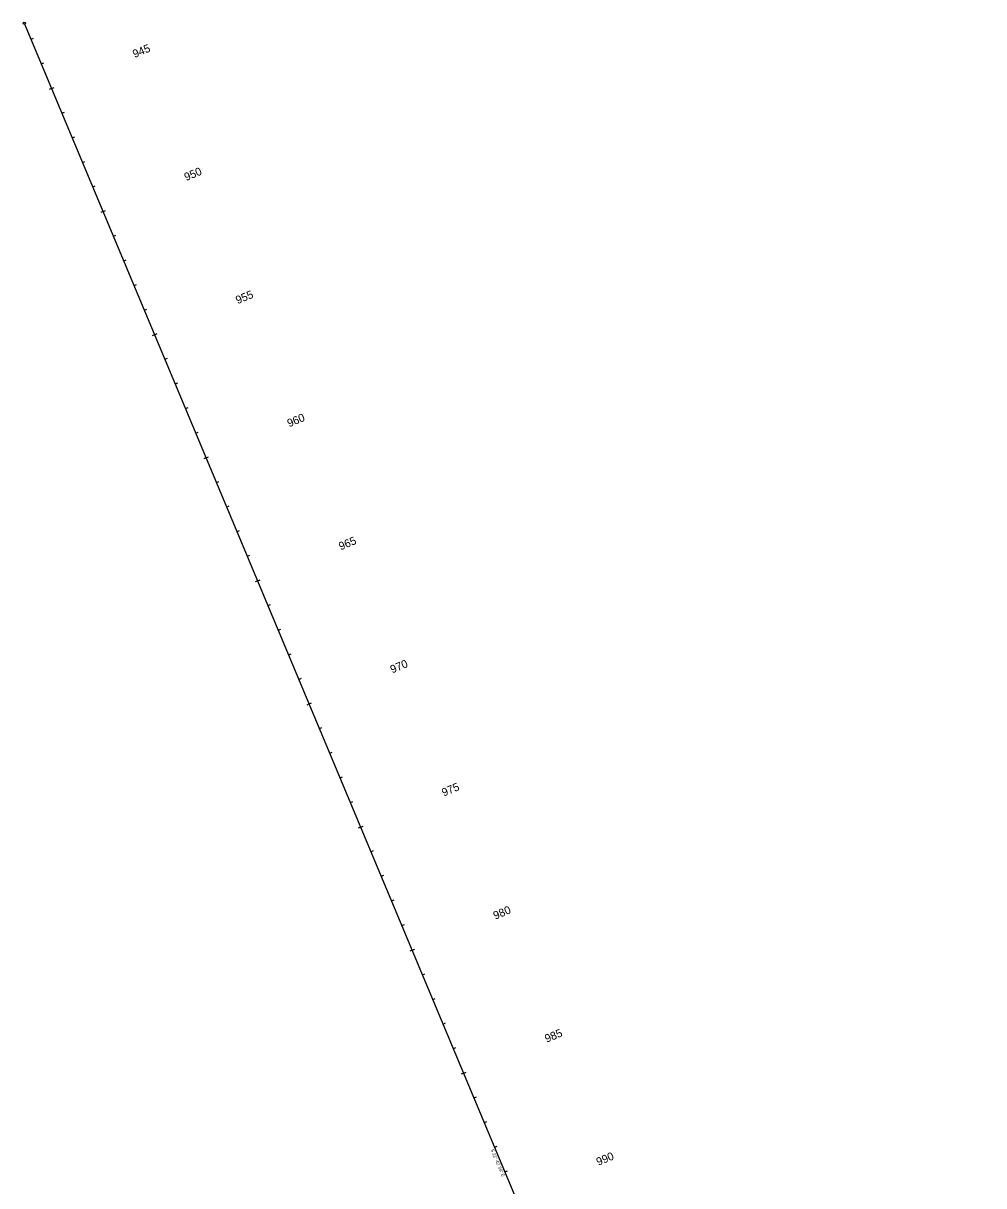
# Model space of a CAD drawing. Extents: x 2819977 to 2827606, y 116785 to 150320.
# Drawn here: x 2821722 to 2825322, y 121023 to 125379 of the extents above; entities that cross this region are included whole.
import ezdxf

# ---------------------------------------------------------------- set-up
doc = ezdxf.new("R2010")
doc.units = 0
for name, color, linetype in [('Modeling-Contours-Minor-Existing', 7, 'Continuous'), ('Modeling-Flow Arrows-Existing', 7, 'Continuous'), ('Modeling-Spot-Existing', 7, 'Continuous')]:
    doc.layers.add(name, color=color, linetype=linetype)

msp = doc.modelspace()

# ---------------------------------------------------------------- linework, layer by layer
at = {"layer": 'Modeling-Flow Arrows-Existing'}
for p, q in [((2821725.8, 125379.3), (2825322, 116789)), ((2821750.9, 125319.2), (2821760.1, 125323.1)), ((2821789.5, 125227), (2821798.8, 125230.8)), ((2821828.2, 125134.7), (2821818.9, 125130.9)), ((2821828.2, 125134.7), (2821837.4, 125138.6)), ((2821866.8, 125042.5), (2821876, 125046.4)), ((2821905.4, 124950.3), (2821914.6, 124954.1)), ((2821944, 124858), (2821953.2, 124861.9)), ((2821982.6, 124765.8), (2821991.8, 124769.6)), ((2822021.2, 124673.5), (2822012, 124669.7)), ((2822021.2, 124673.5), (2822030.5, 124677.4)), ((2822059.9, 124581.3), (2822069.1, 124585.1)), ((2822098.5, 124489), (2822107.7, 124492.9)), ((2822137.1, 124396.8), (2822146.3, 124400.7)), ((2822175.7, 124304.6), (2822184.9, 124308.4)), ((2822214.3, 124212.3), (2822205.1, 124208.4)), ((2822214.3, 124212.3), (2822223.5, 124216.2)), ((2822252.9, 124120.1), (2822262.2, 124123.9)), ((2822291.6, 124027.8), (2822300.8, 124031.7)), ((2822330.2, 123935.6), (2822339.4, 123939.4)), ((2822368.8, 123843.3), (2822378, 123847.2)), ((2822407.4, 123751.1), (2822398.2, 123747.2)), ((2822407.4, 123751.1), (2822416.6, 123755)), ((2822446, 123658.9), (2822455.2, 123662.7)), ((2822484.6, 123566.6), (2822493.9, 123570.5)), ((2822523.3, 123474.4), (2822532.5, 123478.2)), ((2822561.9, 123382.1), (2822571.1, 123386)), ((2822600.5, 123289.9), (2822591.3, 123286)), ((2822600.5, 123289.9), (2822609.7, 123293.7)), ((2822639.1, 123197.6), (2822648.3, 123201.5)), ((2822677.7, 123105.4), (2822687, 123109.3)), ((2822716.3, 123013.2), (2822725.6, 123017)), ((2822755, 122920.9), (2822764.2, 122924.8)), ((2822793.6, 122828.7), (2822784.4, 122824.8)), ((2822793.6, 122828.7), (2822802.8, 122832.5)), ((2822832.2, 122736.4), (2822841.4, 122740.3)), ((2822870.8, 122644.2), (2822880, 122648)), ((2822909.4, 122551.9), (2822918.7, 122555.8)), ((2822948, 122459.7), (2822957.3, 122463.6)), ((2822986.7, 122367.5), (2822977.4, 122363.6)), ((2822986.7, 122367.5), (2822995.9, 122371.3)), ((2823025.3, 122275.2), (2823034.5, 122279.1)), ((2823063.9, 122183), (2823073.1, 122186.8)), ((2823102.5, 122090.7), (2823111.7, 122094.6)), ((2823141.1, 121998.5), (2823150.4, 122002.3)), ((2823179.7, 121906.2), (2823170.5, 121902.4)), ((2823179.7, 121906.2), (2823189, 121910.1)), ((2823218.4, 121814), (2823227.6, 121817.9)), ((2823257, 121721.8), (2823266.2, 121725.6)), ((2823295.6, 121629.5), (2823304.8, 121633.4)), ((2823334.2, 121537.3), (2823343.4, 121541.1)), ((2823372.8, 121445), (2823363.6, 121441.2)), ((2823372.8, 121445), (2823382.1, 121448.9)), ((2823411.4, 121352.8), (2823420.7, 121356.6)), ((2823450.1, 121260.5), (2823459.3, 121264.4)), ((2823488.7, 121168.3), (2823497.9, 121172.2)), ((2823527.3, 121076.1), (2823536.5, 121079.9))]:
    msp.add_line(p, q, dxfattribs=at)
at = {"layer": 'Modeling-Spot-Existing'}
msp.add_circle((2821725.8, 125379.3), 4, dxfattribs=at)

# ---------------------------------------------------------------- texts
at = {"layer": 'Modeling-Contours-Minor-Existing'}
msp.add_text('S 22%%d 42\' 59" E', height=12, rotation=292.7163, dxfattribs=at).set_placement((2823473.4, 121158.2))
at = {"layer": 'Modeling-Flow Arrows-Existing'}
for s, p in [(' 945', (2822129.1, 125244.5)), (' 950', (2822322.2, 124783.3)), (' 955', (2822515.3, 124322)), (' 960', (2822708.4, 123860.8)), (' 965', (2822901.5, 123399.6)), (' 970', (2823094.5, 122938.4)), (' 975', (2823287.6, 122477.2)), (' 980', (2823480.7, 122016)), (' 985', (2823673.8, 121554.8)), (' 990', (2823866.9, 121093.5))]:
    msp.add_text(s, height=30, rotation=22.7163, dxfattribs=at).set_placement(p)

doc.saveas('drawing.dxf')
